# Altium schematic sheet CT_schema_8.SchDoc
size 371 x 336 mm
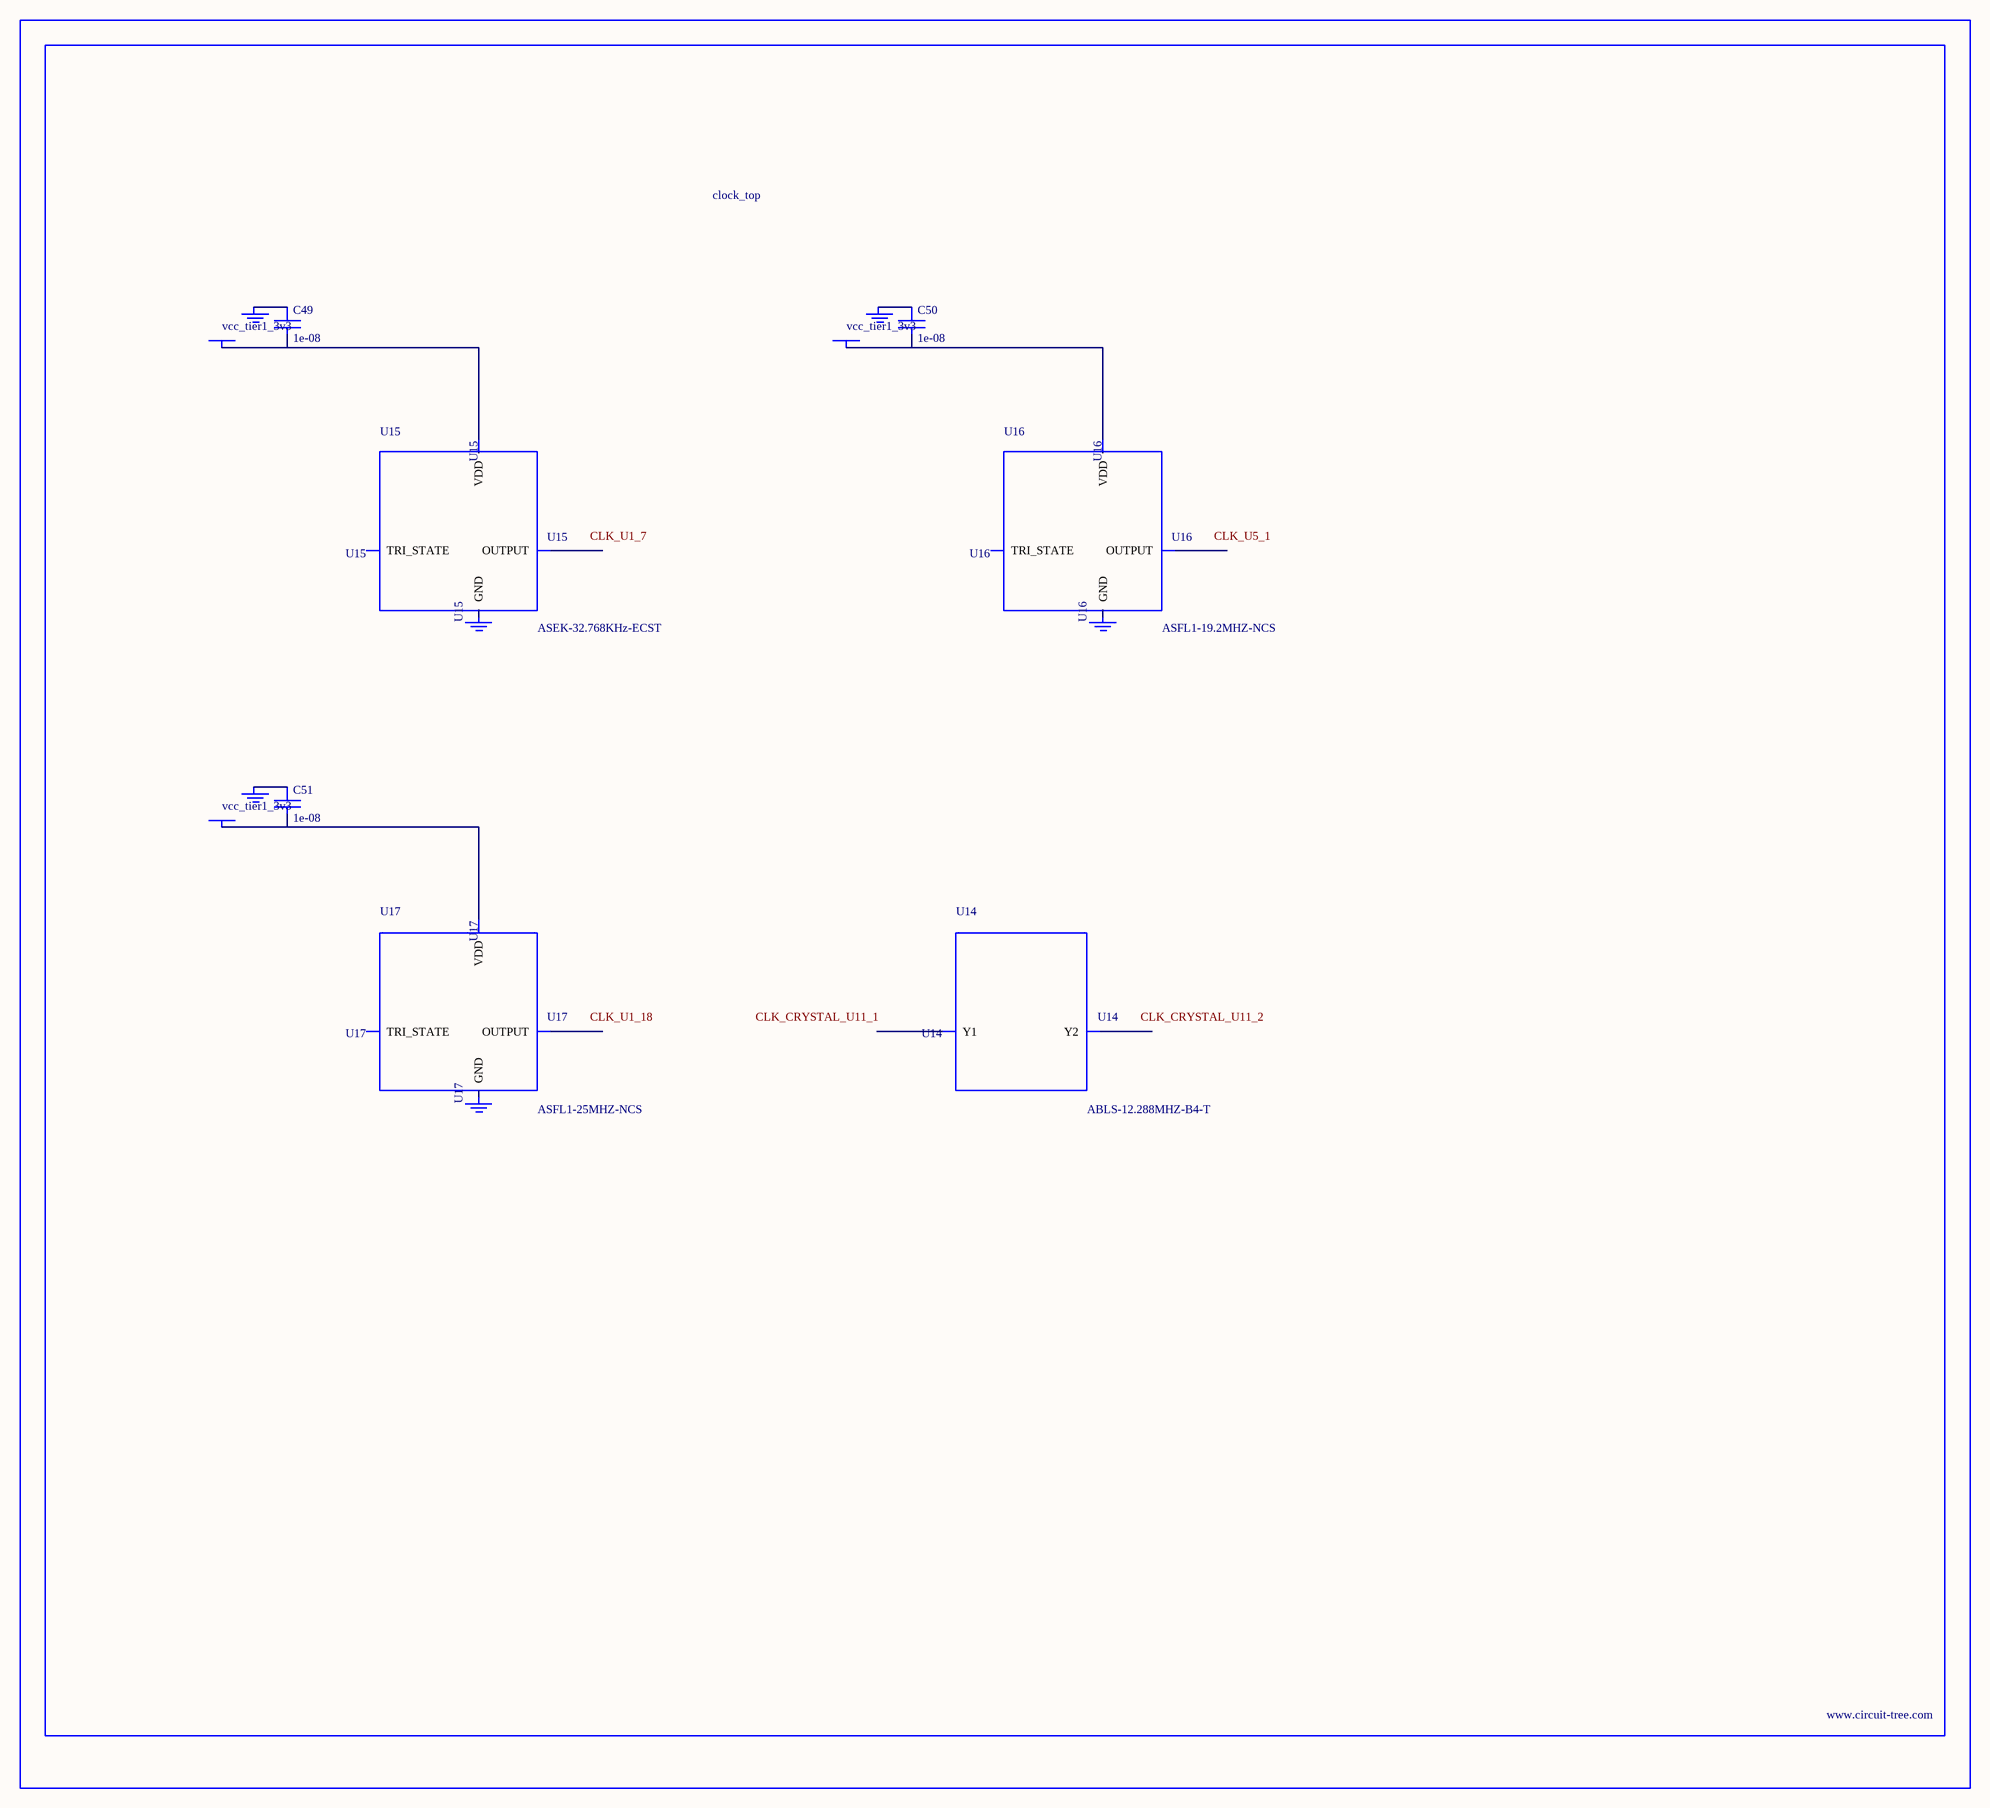
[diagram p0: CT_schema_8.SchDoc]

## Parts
BORDER7  (no value)
C49  1e-08  [C0402]
C50  1e-08  [C0402]
C51  1e-08  [C0402]
GND_INSTANCE_7_0  (no value)
GND_INSTANCE_7_1  (no value)
GND_INSTANCE_7_2  (no value)
GND_INSTANCE_7_3  (no value)
GND_INSTANCE_7_4  (no value)
GND_INSTANCE_7_5  (no value)
POWER_INSTANCE_7_0  vcc_tier1_3v3
POWER_INSTANCE_7_1  vcc_tier1_3v3
POWER_INSTANCE_7_2  vcc_tier1_3v3
U14  ABLS-12.288MHZ-B4-T  [ABLS-12.288MHZ-B4-T]
U15  ASEK-32.768KHz-ECST  [ASEK]
U16  ASFL1-19.2MHZ-NCS  [ASFL1]
U17  ASFL1-25MHZ-NCS  [ASFL1]

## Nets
NetC49_1: C49.1 GND_INSTANCE_7_0.0(GND)
NetC49_2: C49.2 POWER_INSTANCE_7_0.0(PWR) U15.4(VDD)
NetC50_1: C50.1 GND_INSTANCE_7_2.0(GND)
NetC50_2: C50.2 POWER_INSTANCE_7_1.0(PWR) U16.4(VDD)
NetC51_1: C51.1 GND_INSTANCE_7_4.0(GND)
NetC51_2: C51.2 POWER_INSTANCE_7_2.0(PWR) U17.4(VDD)

Not connected (* = marked no-connect by the designer): GND_INSTANCE_7_1 0(GND); GND_INSTANCE_7_3 0(GND); GND_INSTANCE_7_5 0(GND); U14 1(Y1) 2(Y2); U15 1(TRI_STATE) 2(GND) 3(OUTPUT); U16 1(TRI_STATE) 2(GND) 3(OUTPUT); U17 1(TRI_STATE) 2(GND) 3(OUTPUT)

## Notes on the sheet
- Labels drawn without touching a wire or pin: CLK_CRYSTAL_U11_1, CLK_CRYSTAL_U11_2, CLK_U1_7, CLK_U1_18, CLK_U5_1

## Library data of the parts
BORDER7 = BORDER_PAGE7
C49-C51 = C0402C103K3RAC
GND_INSTANCE_7_0-GND_INSTANCE_7_5 = GND
POWER_INSTANCE_7_0-POWER_INSTANCE_7_2 = PWR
